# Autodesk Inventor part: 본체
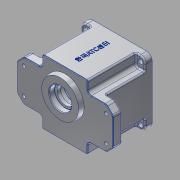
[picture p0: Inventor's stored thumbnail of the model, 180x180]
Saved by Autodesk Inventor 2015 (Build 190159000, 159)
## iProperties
Created: 2016-02
Part Number: 본체
Material: Aluminum 6061
Document SubType Name: Modeling
Designer: Administrator
Density: 2.7 g/cm^3
Appearance: Aluminum - Flat
Mass: 873.708 g
Surface Area: 761.421 cm^2
Volume: 323.596 cm^3
Author: Administrator
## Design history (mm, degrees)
sketch "Sketch1"
  geometry: L1 (-70, -30)-(70, -30); L2 (70, -30)-(70, 30); L3 (70, 30)-(-70, 30); L4 (-70, 30)-(-70, -30); L5 (-70, -30)-(70, 30); L6 (70, -30)-(-70, 30); 1 further point
  constraints: 12 end point, 2 midpoint, 2 parallel, 1 horizontal, 1 perpendicular
  dimensions: "d0" = 140 distance of L2.end L3.end; "d1" = 60 distance of L3.end L1.start
extrude "Extrusion1" new body sketch "Sketch1" distance "d2" = 13; taper "d3" = 0 deg
sketch "Sketch2"
  geometry: L1 (33, -47)-(-33, -47); L2 (-33, -47)-(-33, 47); L3 (-33, 47)-(33, 47); L4 (33, 47)-(33, -47); L5 (33, -47)-(-33, 47); L6 (-33, -47)-(33, 47); 1 further point
  constraints: 12 end point, 2 midpoint, 2 parallel, 1 horizontal, 1 perpendicular
  dimensions: "d4" = 66 distance of L2.end L3.end; "d5" = 94 distance of L3.end L1.start
extrude "Extrusion2" join sketch "Sketch2" distance "d6" = 80; taper "d7" = 0 deg
chamfer "Chamfer1" distance "d8" = 10; stored, may be unused: second distance "d9" = 2, angle "d10" = 45 deg
sketch "Sketch4"
  geometry: L1 (47, -47)-(-47, -47); L2 (-47, -47)-(-47, 47); L3 (-47, 47)-(47, 47); L4 (47, 47)-(47, -47); L5 (47, -47)-(-47, 47); L6 (-47, -47)-(47, 47); 1 further point
  constraints: 12 end point, 2 midpoint, 2 parallel, 1 horizontal, 1 perpendicular
  dimensions: "d11" = 94 distance of L1.end L2.end; "d12" = 94 distance of L2.end L3.end
extrude "Extrusion3" join sketch "Sketch4" distance "d13" = 10; taper "d14" = 0 deg
fillet "Fillet1" dims "d15" = 8
sketch "Sketch5"
  geometry: L1 (47, -30)-(-47, -30); L2 (-47, -30)-(-47, 30); L3 (-47, 30)-(47, 30); L4 (47, 30)-(47, -30); L5 (47, -30)-(-47, 30); L6 (-47, -30)-(47, 30); 1 further point
  constraints: 12 end point, 2 midpoint, 2 parallel, 1 horizontal, 1 perpendicular
  dimensions: "d16" = 60 distance of L3.end L1.start; "d17" = 94 distance of L2.end L3.end
extrude "Extrusion4" join sketch "Sketch5" stored distance "d18" = 62; taper "d19" = 0 deg
sketch "Sketch6"
  geometry: C1 r 43 at (0, 0); 1 further point
  constraints: 1 centre point, 1 coincident
  dimensions: "d20" = 86 diameter of C1
extrude "Extrusion5" cut sketch "Sketch6" distance "d21" = 9; taper "d22" = 0 deg
sketch "Sketch7"
  geometry: C1 r 40 at (0, 0); 1 further point
  constraints: 1 centre point, 1 coincident
  dimensions: "d23" = 80 diameter of C1
extrude "Extrusion6" cut sketch "Sketch7" distance "d24" = 62; taper "d25" = 0 deg
sketch "Sketch8"
  geometry: A1 r 21 centre (0, -11) between (-8.978, 7.984) and (8.978, 7.984); A2 r 15 centre (0, 20) between (8.978, 7.984) and (-8.978, 7.984); 1 further point
  constraints: 4 point on circle, 2 centre point, 2 vertical alignment
  dimensions: "d26" = 42 diameter of A1; "d27" = 11 distance of point (0, 0) A1.centre; "d28" = 30 diameter of A2; "d29" = 20 distance of point (0, 0) A2.centre
extrude "Extrusion7" join sketch "Sketch8" distance "d30" = 7; taper "d31" = 0 deg
fillet "Fillet2" dims "d32" = 3
sketch "Sketch9"
  geometry: C1 r 28 at (0, 11); 1 further point
  constraints: 1 centre point, 1 vertical alignment
  dimensions: "d33" = 56 diameter of C1; "d34" = 11 distance of point (0, 0) C1.centre
extrude "Extrusion8" join sketch "Sketch9" distance "d35" = 7; taper "d36" = -10 deg
sketch "Sketch10"
  geometry: C1 r 17.5 at (0, -11); A1 r 21 centre (0, -11) between (-12.163, 6.119) and (12.163, 6.119) reference; 1 further point
  constraints: 1 centre point, 1 concentric
  dimensions: "d37" = 35 diameter of C1
extrude "Extrusion9" cut sketch "Sketch10" distance "d38" = 10; taper "d39" = 0 deg
sketch "Sketch11"
  geometry: C1 r 12.5 at (0, 0); C2 r 17.5 at (0, 0) reference; 1 further point
  constraints: 1 centre point, 1 concentric
  dimensions: "d40" = 25 diameter of C1
extrude "Extrusion10" cut sketch "Sketch11" distance "d41" = 5; taper "d42" = 0 deg
sketch "Sketch12"
  geometry: C1 r 16 at (0, 0); C2 r 12.5 at (0, 0) reference; 1 further point
  constraints: 1 centre point, 1 concentric
  dimensions: "d43" = 32 diameter of C1
extrude "Extrusion11" cut sketch "Sketch12" distance "d44" = 8; taper "d45" = 0 deg
sketch "Sketch13"
  geometry: C1 r 11 at (0, 20); A1 r 15 centre (0, 20) between (11.584, 10.47) and (-11.584, 10.47) reference; 1 further point
  constraints: 1 centre point, 1 concentric
  dimensions: "d46" = 22 diameter of C1
extrude "Extrusion12" cut sketch "Sketch13" distance "d47" = 7; taper "d48" = 0 deg
sketch "Sketch14"
  geometry: C1 r 9.5 at (0, 0); C2 r 11 at (0, 0) reference; 1 further point
  constraints: 1 centre point, 1 concentric
  dimensions: "d49" = 19 diameter of C1
extrude "Extrusion13" cut sketch "Sketch14" distance "d50" = 1; taper "d51" = 0 deg
chamfer "Chamfer2" distance "d52" = 1; stored, may be unused: second distance "d53" = 2, angle "d54" = 45 deg
fillet "Fillet3" dims "d55" = 2
sketch "Sketch17"
  geometry: C1 r 4.5 at (60, 19); C2 r 4.5 at (60, -19); C3 r 4.5 at (-60, -19); C4 r 4.5 at (-60, 19); C5 r 12.5 at (0, -11) reference; 1 further point
  constraints: 4 centre point, 2 horizontal alignment, 2 vertical alignment
  dimensions: "d72" = 9 diameter of C2; "d73" = 9 diameter of C1; "d74" = 9 diameter of C4; "d75" = 9 diameter of C3; "d76" = 38 distance of C2.centre C1.centre; "d77" = 19 vertical distance of point (0, 0) C1.centre; "d78" = 120 distance of C1.centre C4.centre; "d79" = 60 horizontal distance of C5.centre C4.centre
extrude "Extrusion16" cut sketch "Sketch17" distance "d80" = 4; taper "d81" = 0 deg
sketch "Sketch18"
  geometry: C1 r 4.5 at (0, 0) reference; C2 r 4.5 at (0, -38) reference; C3 r 4.5 at (-120, -38) reference; C4 r 4.5 at (-120, 0) reference; C5 r 2.5 at (0, 0); C6 r 2.5 at (0, -38); C7 r 2.5 at (-120, 0); C8 r 2.5 at (-120, -38); 1 further point
  constraints: 4 centre point, 4 coincident
  dimensions: "d82" = 5 diameter of C8; "d83" = 5 diameter of C7; "d84" = 5 diameter of C6; "d85" = 5 diameter of C5
extrude "Extrusion17" cut sketch "Sketch18" stored distance "d86" = 4; taper "d87" = 0 deg
sketch "Sketch19"
  geometry: C1 r 3.5 at (-40, 40); C2 r 3.5 at (40, 40); C3 r 3.5 at (40, -40); C4 r 3.5 at (-40, -40); 1 further point
  constraints: 4 centre point, 2 horizontal alignment, 2 vertical alignment
  dimensions: "d134" = 7 diameter of C1; "d135" = 7 diameter of C2; "d136" = 7 diameter of C3; "d137" = 7 diameter of C4; "d138" = 80 distance of C1.centre C2.centre; "d139" = 80 distance of C3.centre C2.centre; "d140" = 40 horizontal distance of C1.centre point (0, 0); "d141" = 40 horizontal distance of point (0, 0) C1.centre
extrude "Extrusion18" cut sketch "Sketch19" stored distance "d92" = 4; taper "d93" = 0 deg
sketch "Sketch20"
  geometry: A1 r 36 centre (0, 0) between (36, 0) and (-36, 0); A2 r 4 centre (36, 0) between (35.852, 3.997) and (35.852, -3.997); A3 r 4 centre (-36, 0) between (-35.852, -3.997) and (-35.852, 3.997); A4 r 3.5 centre (-35.722, -7.495) between (-35.778, -3.995) and (-39.148, -8.214); A5 r 40 centre (0, 0) between (-39.148, -8.214) and (39.148, -8.214) reference; A6 r 3.5 centre (-35.722, 7.495) between (-39.148, 8.214) and (-35.778, 3.995); A7 r 3.5 centre (35.722, -7.495) between (39.148, -8.214) and (35.778, -3.995); A8 r 3.5 centre (35.722, 7.495) between (35.778, 3.995) and (39.148, 8.214); 1 further point
  constraints: 26 point on circle, 8 tangent, 7 centre point, 2 horizontal alignment, 1 coincident
  dimensions: "d94" = 36 radius of A1; "d95" = 4 radius of A2; "d96" = 4 radius of A3; "d97" = 3.5 radius of A4; "d98" = 3.5 radius of A6; "d99" = 3.5 radius of A7; "d100" = 3.5 radius of A8
extrude "Extrusion19" join sketch "Sketch20" stored distance "d101" = 4; taper "d102" = 0 deg
sketch "Sketch21"
  geometry: A1 r 4 centre (36, 0) between (35.852, 3.997) and (35.852, -3.997) reference; A2 r 4 centre (-36, 0) between (-35.852, -3.997) and (-35.852, 3.997) reference; A3 r 4 centre (-36, 0) between (-35.852, -3.997) and (-35.852, 3.997) reference; 3 further points
  constraints: 2 coincident
hole "Hole1" sketch "Sketch21" at (36, 0), (-36, 0) diameter "d103" = 3.242; stored, may be unused: countersink angle "d107" = 90 deg, drill point angle "d109" = 118 deg; dims "d104" = 7, "d105" = 4, "d106" = 2, "d108" = 9
fillet "Fillet4" dims "d113" = 0.3
fillet "Fillet5" dims "d114" = 5
fillet "Fillet6" dims "d118" = 5
fillet "Fillet7" dims "d119" = 2
fillet "Fillet8" dims "d120" = 2
fillet "Fillet9" dims "d121" = 2
fillet "Fillet10" dims "d122" = 2
chamfer "Chamfer3" distance "d123" = 1; stored, may be unused: second distance "d124" = 2, angle "d125" = 45 deg
fillet "Fillet11" dims "d126" = 2
fillet "Fillet12" dims "d127" = 2
sketch "Sketch24"
  geometry: L1 (-31, 47)-(31, 47) reference; L2 (-33, 35)-(-33, 45) reference; L3 (-57.929, 30)-(-38, 30) reference; L4 (-68.536, 21.464)-(-61.464, 28.536) reference; L5 (-70, -17.929)-(-70, 17.929) reference; L6 (-61.464, -28.536)-(-68.536, -21.464) reference; L7 (-38, -30)-(-57.929, -30) reference; L8 (-33, -45)-(-33, -35) reference; L9 (31, -47)-(-31, -47) reference; L10 (33, -35)-(33, -45) reference; L11 (57.929, -30)-(38, -30) reference; L12 (68.536, -21.464)-(61.464, -28.536) reference; L13 (70, 17.929)-(70, -17.929) reference; L14 (61.464, 28.536)-(68.536, 21.464) reference; L15 (38, 30)-(57.929, 30) reference; L16 (33, 45)-(33, 35) reference; L17 (-32, -45)-(-32, -35); L18 (-38, -29)-(-57.929, -29); L19 (-60.757, -27.828)-(-67.828, -20.757); L20 (-69, -17.929)-(-69, 17.929); L21 (-67.828, 20.757)-(-60.757, 27.828); L22 (-57.929, 29)-(-38, 29); L23 (-32, 35)-(-32, 45); L24 (-31, 46)-(31, 46); L25 (32, 45)-(32, 35); L26 (38, 29)-(57.929, 29); L27 (60.757, 27.828)-(67.828, 20.757); L28 (69, 17.929)-(69, -17.929); L29 (67.828, -20.757)-(60.757, -27.828); L30 (57.929, -29)-(38, -29); L31 (32, -35)-(32, -45); L32 (31, -46)-(-31, -46); C1 r 2.5 at (-60, 19) reference; C2 r 2.5 at (60, -19) reference; C3 r 2.5 at (60, 19) reference; C4 r 2.5 at (-60, -19) reference; C5 r 28 at (0, 11) reference; A1 r 2 centre (31, 45) between (33, 45) and (31, 47) reference; A2 r 2 centre (-31, 45) between (-31, 47) and (-33, 45) reference; A3 r 5 centre (-38, 35) between (-38, 30) and (-33, 35) reference; A4 r 5 centre (-57.929, 25) between (-57.929, 30) and (-61.464, 28.536) reference; A5 r 5 centre (-65, 17.929) between (-68.536, 21.464) and (-70, 17.929) reference; A6 r 5 centre (-65, -17.929) between (-70, -17.929) and (-68.536, -21.464) reference; A7 r 5 centre (-57.929, -25) between (-61.464, -28.536) and (-57.929, -30) reference; A8 r 5 centre (-38, -35) between (-33, -35) and (-38, -30) reference; A9 r 2 centre (-31, -45) between (-33, -45) and (-31, -47) reference; A10 r 2 centre (31, -45) between (31, -47) and (33, -45) reference; A11 r 5 centre (38, -35) between (38, -30) and (33, -35) reference; A12 r 5 centre (57.929, -25) between (57.929, -30) and (61.464, -28.536) reference; A13 r 5 centre (65, -17.929) between (68.536, -21.464) and (70, -17.929) reference; A14 r 5 centre (65, 17.929) between (70, 17.929) and (68.536, 21.464) reference; A15 r 5 centre (57.929, 25) between (61.464, 28.536) and (57.929, 30) reference; A16 r 5 centre (38, 35) between (33, 35) and (38, 30) reference; A17 r 1 centre (-31, -45) between (-32, -45) and (-31, -46); A18 r 6 centre (-38, -35) between (-32, -35) and (-38, -29); A19 r 4 centre (-57.929, -25) between (-60.757, -27.828) and (-57.929, -29); A20 r 4 centre (-65, -17.929) between (-69, -17.929) and (-67.828, -20.757); A21 r 4 centre (-65, 17.929) between (-67.828, 20.757) and (-69, 17.929); A22 r 4 centre (-57.929, 25) between (-57.929, 29) and (-60.757, 27.828); A23 r 6 centre (-38, 35) between (-38, 29) and (-32, 35); A24 r 1 centre (-31, 45) between (-31, 46) and (-32, 45); A25 r 1 centre (31, 45) between (32, 45) and (31, 46); A26 r 6 centre (38, 35) between (32, 35) and (38, 29); A27 r 4 centre (57.929, 25) between (60.757, 27.828) and (57.929, 29); A28 r 4 centre (65, 17.929) between (69, 17.929) and (67.828, 20.757); A29 r 4 centre (65, -17.929) between (67.828, -20.757) and (69, -17.929); A30 r 4 centre (57.929, -25) between (57.929, -29) and (60.757, -27.828); A31 r 6 centre (38, -35) between (38, -29) and (32, -35); A32 r 1 centre (31, -45) between (31, -46) and (32, -45); 1 further point
  constraints: 32 end point, 32 point on circle, 16 centre point, 31 other
  dimensions: "d128" = 1 distance between parallel lines of L9 L32
extrude "Extrusion22" cut sketch "Sketch24" distance "d129" = 1; taper "d130" = 0 deg
sketch "Sketch25"
  geometry: L1 (78, 0)-(0, 0) reference; 2 further points
  constraints: 1 vertical alignment, 1 other
  dimensions: "d131" = 40 distance from line of L1 point (39, -40)
emboss "Emboss1" sketch "Sketch25" dims "d132" = 0.5, "d133" = 0
body "Solid1"
node "Projected Loop3"
